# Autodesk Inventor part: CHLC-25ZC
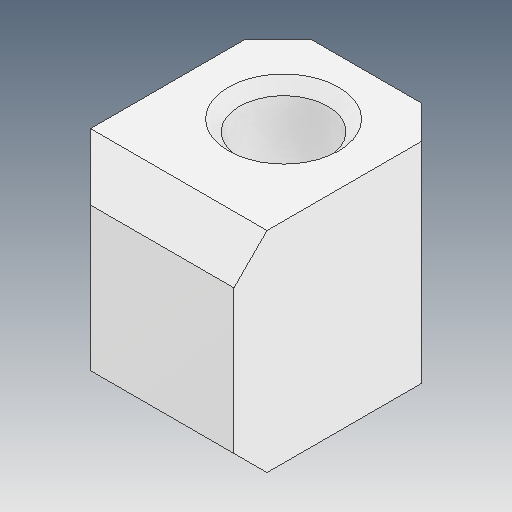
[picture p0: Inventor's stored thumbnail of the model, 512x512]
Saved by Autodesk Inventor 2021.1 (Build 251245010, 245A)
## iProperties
Created: 2021-05
Part Number: CHLC-25ZC
Material: Ogólny
Document SubType Name: Modeling
Designer: user
Density: 1 g/cm^3
Appearance: Domyślna
Author: user
Revision Number: ÈÎºÎ
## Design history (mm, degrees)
feature "ÊäÈë1"
node "Bryła1"
